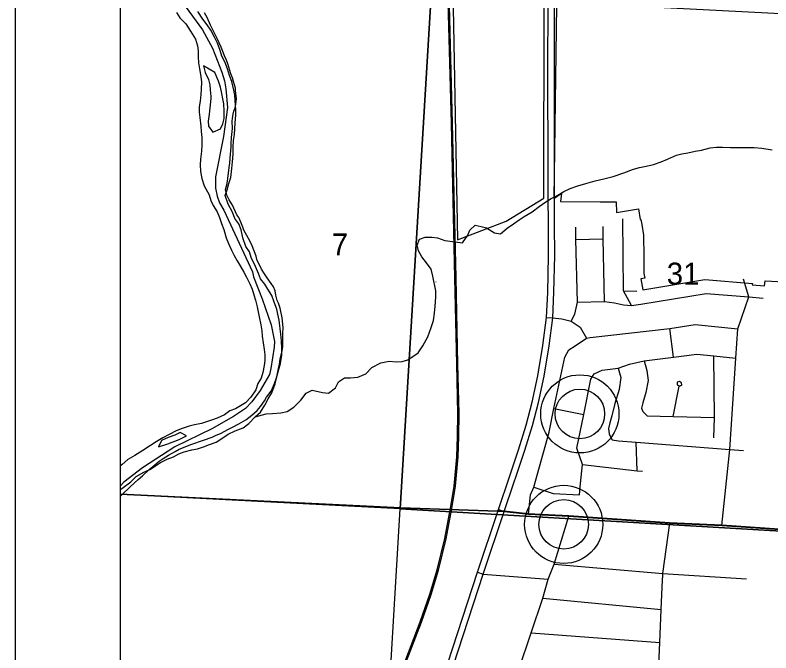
# Model space of a CAD drawing. Extents: x 0 to 42.5, y 0 to 22.
# Drawn here: x 2 to 2.72, y 18.908 to 19.515 of the extents above; entities that cross this region are included whole.
import ezdxf

# ---------------------------------------------------------------- set-up
doc = ezdxf.new("R2010")
doc.units = 0
for name, color, linetype in [('Default', 7, 'Continuous'), ('GM_X_County_Road', 7, 'Continuous'), ('GM_X_Interchange_Ramps', 7, 'Continuous'), ('GM_X_Major_River', 7, 'Continuous'), ('GM_X_Minor_River', 7, 'Continuous'), ('GM_X_Rail_Line', 7, 'Continuous'), ('GM_X_Section', 7, 'Continuous'), ('GM_X_Section_Text', 7, 'Continuous'), ('GM_X_Township_Road', 7, 'Continuous'), ('GM_X_Unincorporated', 7, 'Continuous'), ('GM_X_Unincorporated_Location', 7, 'Continuous'), ('GM_X_US_Route', 7, 'Continuous'), ('SH_Cut_Line', 7, 'Continuous'), ('SH_Data', 7, 'Continuous')]:
    doc.layers.add(name, color=color, linetype=linetype)

msp = doc.modelspace()

# ---------------------------------------------------------------- linework, layer by layer
at = {"layer": 'Default'}
for points in [[(2.41264, 19.76072), (2.42127, 19.30123), (2.46743, 19.31905), (2.50341, 19.34075), (2.50358, 19.5252)], [(2.51542, 19.52474), (2.51301, 19.34066), (2.52032, 19.34565), (2.51936, 19.33772), (2.55692, 19.33747), (2.57234, 19.33736), (2.57249, 19.32735), (2.59349, 19.33083), (2.59519, 19.32056), (2.59583, 19.32066), (2.5966, 19.31599), (2.5983, 19.30571), (2.59837, 19.29998), (2.59846, 19.29108), (2.59871, 19.26931), (2.59948, 19.26463), (2.59577, 19.26402), (2.59748, 19.25374), (2.6568, 19.26357), (2.70192, 19.25981), (2.7018, 19.25839), (2.7135, 19.25742), (2.71398, 19.26227), (2.75552, 19.25999)]]:
    msp.add_lwpolyline(points, dxfattribs=at)
at = {"layer": 'GM_X_County_Road'}
msp.add_lwpolyline([(2.46029, 19.0444), (2.46567, 19.0426), (2.48865, 19.04002), (2.52727, 19.03819), (2.62319, 19.03155), (2.67298, 19.02943), (2.73268, 19.0251)], dxfattribs=at)
at = {"layer": 'GM_X_Interchange_Ramps'}
for points in [[(2.15946, 19.52708), (2.17844, 19.5013), (2.18781, 19.48357), (2.19677, 19.46089), (2.19937, 19.45251), (2.20065, 19.4449), (2.20225, 19.42722), (2.19849, 19.39949), (2.19068, 19.36115), (2.1908, 19.35051), (2.19227, 19.3429), (2.19451, 19.33642), (2.19863, 19.32936), (2.22595, 19.27084), (2.22705, 19.26589), (2.23527, 19.24512), (2.24365, 19.22036), (2.24696, 19.20456), (2.24674, 19.19905), (2.24359, 19.17873), (2.24204, 19.17304), (2.23323, 19.15789), (2.22521, 19.14692), (2.2193, 19.14068), (2.20788, 19.13316), (2.18716, 19.12131), (2.152, 19.10424), (2.12118, 19.0841), (2.10348, 19.07053), (2.1, 19.06675), (2.1, 19.05902), (2.36716, 19.04598), (2.45932, 19.04306), (2.46556, 19.04286), (2.48854, 19.04029), (2.52716, 19.03846), (2.62308, 19.03181), (2.67287, 19.02969), (2.74103, 19.02475)], [(3.37078, 18.98615), (3.11995, 19.00104), (2.94956, 19.01199), (2.74103, 19.02475), (2.67287, 19.02969), (2.62308, 19.03181), (2.52716, 19.03846), (2.48854, 19.04029), (2.46556, 19.04286), (2.45932, 19.04306), (2.36716, 19.04598), (2.1, 19.05902), (2.1, 16.00757)]]:
    msp.add_lwpolyline(points, dxfattribs=at)
at = {"layer": 'GM_X_Major_River'}
for points in [[(2.1538, 19.51765), (2.1568, 19.51269), (2.16264, 19.50695), (2.16695, 19.49989), (2.17184, 19.49226), (2.1735, 19.48579), (2.17442, 19.48103), (2.17439, 19.47552), (2.17454, 19.46962), (2.17565, 19.46411), (2.17674, 19.45688), (2.17746, 19.45136), (2.17723, 19.44471), (2.17682, 19.43958), (2.17603, 19.43312), (2.17524, 19.428), (2.17521, 19.42268), (2.17575, 19.41754)], [(2.24651, 19.24185), (2.24427, 19.24814), (2.24052, 19.25424), (2.2377, 19.25901), (2.23375, 19.26398), (2.2317, 19.26912), (2.2289, 19.2758), (2.22478, 19.28456), (2.22311, 19.2899), (2.21973, 19.29486), (2.21693, 19.30305), (2.21509, 19.31067), (2.21304, 19.31657), (2.20909, 19.32154), (2.20685, 19.32763), (2.20292, 19.33526), (2.19993, 19.34345), (2.20186, 19.34895), (2.20341, 19.35483), (2.20534, 19.36071), (2.20634, 19.36907), (2.20695, 19.37553), (2.20756, 19.38294), (2.2076, 19.3894), (2.20783, 19.39567), (2.20881, 19.40136), (2.20963, 19.41276), (2.21025, 19.41979), (2.21027, 19.42473), (2.20922, 19.4388), (2.2083, 19.44375), (2.20646, 19.45193), (2.20403, 19.45765), (2.20217, 19.46412), (2.19956, 19.4706), (2.19694, 19.47613), (2.19527, 19.48146), (2.19266, 19.48832), (2.18985, 19.49404), (2.18629, 19.50072), (2.18291, 19.50587), (2.17877, 19.51141), (2.17408, 19.51866)], [(2.17945, 19.46693), (2.18093, 19.46065), (2.18411, 19.45398), (2.18541, 19.44865), (2.18576, 19.44389), (2.18629, 19.43781), (2.18643, 19.43576)], [(2.18643, 19.43576), (2.18486, 19.42071), (2.18387, 19.41426), (2.18403, 19.40951), (2.18836, 19.40359), (2.19558, 19.40696), (2.19788, 19.4117), (2.19905, 19.41663), (2.19909, 19.42366), (2.19856, 19.4307), (2.19764, 19.43546), (2.19673, 19.4404), (2.19562, 19.44649), (2.19377, 19.45221), (2.19002, 19.4604), (2.17945, 19.46693)], [(2.17575, 19.41754), (2.17683, 19.40955), (2.17718, 19.40442), (2.1779, 19.39852), (2.17786, 19.39149), (2.17745, 19.3856), (2.17664, 19.378), (2.17604, 19.3725), (2.17639, 19.36641), (2.17767, 19.35956), (2.18009, 19.3527), (2.18459, 19.34412), (2.18626, 19.33879), (2.18851, 19.33383), (2.19226, 19.32792), (2.19469, 19.32239), (2.19636, 19.31668), (2.19879, 19.31096), (2.20083, 19.30315), (2.20326, 19.29763), (2.20606, 19.29134), (2.20869, 19.28638), (2.2115, 19.28123), (2.21412, 19.27646), (2.21769, 19.27055), (2.22031, 19.26578), (2.22331, 19.25949), (2.22555, 19.25415), (2.22722, 19.24882), (2.2289, 19.24386), (2.23037, 19.23758), (2.23148, 19.23263), (2.2324, 19.22788), (2.23387, 19.22045), (2.23498, 19.21475), (2.23532, 19.20961), (2.23623, 19.20333), (2.23714, 19.19687), (2.23787, 19.19192), (2.23765, 19.18641), (2.23724, 19.18166), (2.23587, 19.17483), (2.23414, 19.16952), (2.23107, 19.1644), (2.22914, 19.15833), (2.22455, 19.15133), (2.21922, 19.14623), (2.2099, 19.1404), (2.20439, 19.13835), (2.19944, 19.13458), (2.19241, 19.13158), (2.18691, 19.12971), (2.1776, 19.12654), (2.17077, 19.12507), (2.16565, 19.12377), (2.15919, 19.12153), (2.15331, 19.11929), (2.14665, 19.11591), (2.14076, 19.11271), (2.1343, 19.10895), (2.12878, 19.10557), (2.12155, 19.10086), (2.11394, 19.09597), (2.10729, 19.09202), (2.10177, 19.08731), (2.1, 19.08564)], [(2.1, 19.06297), (2.10163, 19.06469), (2.11019, 19.07091), (2.11515, 19.07582), (2.12257, 19.08014), (2.12827, 19.08257), (2.13378, 19.08596), (2.13854, 19.08935), (2.14481, 19.09254), (2.15089, 19.09478), (2.15602, 19.09741), (2.16096, 19.09947), (2.16817, 19.10132), (2.17367, 19.10224), (2.17937, 19.10429), (2.18506, 19.10654), (2.19133, 19.10878), (2.19665, 19.11198), (2.20293, 19.11631), (2.20939, 19.11931), (2.21718, 19.1223), (2.22251, 19.12626), (2.22861, 19.13268), (2.23357, 19.13721), (2.23759, 19.14402), (2.24103, 19.14989), (2.24448, 19.15557), (2.24756, 19.16411), (2.2495, 19.17208), (2.25086, 19.17682), (2.2526, 19.18346), (2.25379, 19.19144), (2.25382, 19.19752), (2.25349, 19.20512), (2.25296, 19.21159), (2.25152, 19.2249), (2.25023, 19.23061), (2.24931, 19.23537), (2.24651, 19.24185)], [(2.1563, 19.11124), (2.1563, 19.11124), (2.16315, 19.11462), (2.1571, 19.11789), (2.15197, 19.11545), (2.1457, 19.11302), (2.13944, 19.11021), (2.13637, 19.10415)], [(2.13637, 19.10415), (2.14529, 19.10713), (2.1563, 19.11124)]]:
    msp.add_lwpolyline(points, dxfattribs=at)
at = {"layer": 'GM_X_Minor_River'}
for points in [[(2.39768, 19.26673), (2.39601, 19.2732), (2.39169, 19.2795), (2.38737, 19.28504), (2.38399, 19.29076), (2.38269, 19.29628), (2.385, 19.30197), (2.39032, 19.30384), (2.39676, 19.3038), (2.40207, 19.30319), (2.40925, 19.30048), (2.4191, 19.29928), (2.42591, 19.29829), (2.43088, 19.30567), (2.433, 19.31059), (2.43814, 19.31512), (2.44363, 19.31395), (2.44893, 19.31277), (2.45648, 19.30797), (2.46215, 19.3068), (2.46844, 19.31227), (2.47453, 19.31641), (2.47986, 19.32018), (2.4848, 19.32357), (2.49222, 19.32789), (2.49888, 19.33298), (2.50516, 19.33731), (2.51049, 19.34051), (2.51657, 19.34389), (2.52228, 19.34727), (2.52855, 19.35008), (2.53576, 19.3527), (2.54336, 19.35493), (2.55209, 19.35734), (2.56044, 19.35938), (2.56936, 19.3616), (2.57961, 19.36496), (2.58873, 19.36851), (2.59442, 19.37019), (2.60087, 19.37128), (2.60789, 19.37295), (2.61492, 19.37556), (2.621, 19.378), (2.62955, 19.38174), (2.63486, 19.38323), (2.64036, 19.38395), (2.64738, 19.38562), (2.65345, 19.38672), (2.6618, 19.38876), (2.66787, 19.38948), (2.67337, 19.38944), (2.68094, 19.3892), (2.70368, 19.38906), (2.71088, 19.38844), (2.72072, 19.38705)], [(2.22861, 19.13268), (2.23905, 19.13546), (2.24493, 19.1358), (2.25289, 19.13651), (2.25896, 19.1378), (2.26543, 19.14194), (2.27191, 19.14875), (2.27725, 19.15517), (2.28277, 19.15799), (2.2928, 19.15583), (2.29848, 19.15542), (2.30495, 19.16032), (2.30802, 19.166), (2.31353, 19.16976), (2.31922, 19.16992), (2.32642, 19.17044), (2.33383, 19.17382), (2.33955, 19.17967), (2.34811, 19.18418), (2.35626, 19.18565), (2.36289, 19.18503), (2.36839, 19.18538), (2.37389, 19.18686), (2.38379, 19.19383), (2.38818, 19.20027), (2.39278, 19.20898), (2.39625, 19.2177), (2.39818, 19.22453), (2.39917, 19.23156), (2.39978, 19.2382), (2.4004, 19.24675), (2.40062, 19.25264), (2.39769, 19.26664)], [(2.40051, 19.26125), (2.40061, 19.26105)]]:
    msp.add_lwpolyline(points, dxfattribs=at)
at = {"layer": 'GM_X_Rail_Line'}
for points in [[(2.1, 18.17792), (2.14457, 18.29396), (2.17654, 18.37756), (2.33207, 18.78921), (2.36704, 18.88549), (2.3869, 18.93734), (2.39596, 18.96355), (2.40293, 18.98689), (2.41025, 19.01669), (2.41583, 19.04561), (2.41931, 19.0667), (2.42175, 19.09458), (2.42245, 19.11392), (2.42262, 19.13604), (2.42161, 19.1829), (2.41977, 19.26504), (2.41656, 19.41217), (2.41219, 19.57384)], [(2.1, 18.18164), (2.15385, 18.32227), (2.17403, 18.37922), (2.33229, 18.79774), (2.36592, 18.88591), (2.38577, 18.93774), (2.39482, 18.96391), (2.40178, 18.98721), (2.40908, 19.01694), (2.41465, 19.04582), (2.41812, 19.06685), (2.42055, 19.09465), (2.42125, 19.11394), (2.42142, 19.13604), (2.42041, 19.18287), (2.41857, 19.26502), (2.41536, 19.41214), (2.41099, 19.57381)]]:
    msp.add_lwpolyline(points, dxfattribs=at)
at = {"layer": 'GM_X_Section'}
msp.add_lwpolyline([(2.39595, 19.53408), (2.36652, 19.04519), (2.10192, 19.05874), (2.10942, 19.06612), (2.11722, 19.07309), (2.12121, 19.07648), (2.12749, 19.08251), (2.1311, 19.08534), (2.137, 19.09042), (2.1408, 19.09324), (2.14593, 19.09625), (2.15238, 19.09963), (2.15618, 19.10188), (2.16814, 19.10675), (2.17933, 19.11067), (2.18768, 19.11329), (2.19129, 19.11516), (2.19546, 19.11685), (2.20306, 19.12117), (2.20761, 19.12323), (2.21312, 19.12604), (2.21958, 19.12999), (2.22528, 19.13432), (2.23042, 19.13884), (2.23365, 19.14261), (2.23728, 19.14789), (2.23938, 19.15148), (2.24186, 19.15469), (2.24357, 19.15696), (2.2451, 19.15998), (2.24702, 19.16452), (2.24932, 19.17075), (2.25068, 19.1787), (2.25165, 19.18287), (2.25243, 19.18797), (2.25379, 19.19384), (2.25476, 19.19952), (2.25501, 19.21202), (2.25504, 19.2177), (2.25413, 19.22698), (2.25248, 19.23608), (2.2506, 19.24102), (2.24948, 19.24348), (2.24818, 19.2486), (2.24744, 19.25278), (2.24594, 19.25638), (2.24388, 19.2598), (2.23992, 19.26493), (2.23729, 19.26873), (2.23466, 19.27329), (2.23372, 19.27557), (2.23147, 19.27955), (2.23016, 19.28259), (2.22942, 19.28563), (2.22792, 19.2898), (2.22661, 19.29284), (2.2253, 19.29644), (2.2223, 19.30252), (2.2176, 19.3105), (2.21667, 19.31315), (2.2148, 19.31808), (2.21293, 19.32245), (2.21124, 19.32511), (2.20692, 19.33422), (2.20373, 19.33935), (2.20167, 19.34372), (2.20036, 19.34921), (2.20153, 19.35375), (2.20211, 19.35716), (2.2025, 19.35962), (2.20388, 19.37003), (2.20446, 19.3742), (2.20486, 19.37912), (2.20568, 19.38991), (2.20569, 19.39294), (2.2061, 19.39862), (2.20708, 19.40733), (2.20674, 19.41415), (2.20694, 19.4168), (2.20772, 19.42096), (2.2083, 19.4238), (2.20945, 19.42682), (2.21004, 19.43023), (2.21063, 19.43572), (2.20991, 19.44311), (2.20973, 19.44576), (2.20806, 19.45183), (2.20694, 19.45544), (2.20544, 19.45923), (2.20358, 19.46568), (2.20246, 19.46891), (2.20114, 19.47213), (2.19946, 19.4765), (2.19628, 19.48465), (2.19234, 19.49282), (2.18934, 19.49927), (2.18597, 19.50554), (2.18297, 19.51294), (2.18015, 19.51731)], dxfattribs=at)
for points in [[(2.39595, 19.53408), (2.90759, 19.50738), (2.87643, 19.01565), (2.83799, 19.01773), (2.36652, 19.04519)], [(2.36652, 19.04519), (2.83799, 19.01773), (2.81447, 18.53809), (2.33788, 18.56407)]]:
    msp.add_lwpolyline(points, close=True, dxfattribs=at)
at = {"layer": 'GM_X_Township_Road'}
for p, q in [((2.53394, 19.3015), (2.55991, 19.30233)), ((2.57912, 19.25274), (2.59194, 19.25229)), ((2.62679, 19.18966), (2.62342, 19.2169)), ((2.51299, 19.14065), (2.5415, 19.13505)), ((2.5923, 19.08131), (2.59117, 19.10855)), ((2.51324, 18.99239), (2.52727, 19.03819)), ((2.5076, 18.97829), (2.51324, 18.99239)), ((2.5076, 18.97829), (2.51324, 18.99239)), ((2.5024, 18.9603), (2.61523, 18.94922)), ((2.49145, 18.92723), (2.61384, 18.91784))]:
    msp.add_line(p, q, dxfattribs=at)
for points in [[(2.58668, 19.23866), (2.57912, 19.25274), (2.57865, 19.32136)], [(2.52949, 19.22384), (2.53288, 19.23061), (2.53542, 19.24205), (2.53394, 19.3015), (2.53394, 19.31318)], [(2.56126, 19.24269), (2.55991, 19.30233), (2.56001, 19.31401)], [(2.67298, 19.02943), (2.68043, 19.1017), (2.68615, 19.18863), (2.6882, 19.21637), (2.69851, 19.24713), (2.69341, 19.26367)], [(2.53542, 19.24205), (2.56126, 19.24269), (2.57058, 19.24142), (2.57927, 19.2393), (2.58668, 19.23866), (2.59579, 19.23993), (2.65806, 19.2501), (2.69851, 19.24713), (2.71206, 19.24586)], [(2.50597, 19.22738), (2.51186, 19.2271), (2.52039, 19.22617), (2.52949, 19.22384), (2.53797, 19.21812), (2.54411, 19.20774)], [(2.54751, 19.20813), (2.62342, 19.2169), (2.6474, 19.22079), (2.6882, 19.21637)], [(2.48865, 19.04002), (2.49073, 19.05842), (2.49381, 19.06594), (2.50838, 19.11801), (2.51299, 19.14065), (2.52341, 19.18958), (2.52724, 19.1964), (2.53334, 19.20036), (2.54411, 19.20774), (2.54751, 19.20813)], [(2.53722, 19.05842), (2.53828, 19.06943), (2.54019, 19.08754), (2.53488, 19.10284), (2.5415, 19.13505), (2.54817, 19.16872), (2.55142, 19.17383), (2.55885, 19.17721), (2.57407, 19.17911), (2.5849, 19.18295), (2.59892, 19.18604), (2.62679, 19.18966), (2.64914, 19.19227), (2.66514, 19.19069), (2.68615, 19.18863)], [(2.66521, 19.11272), (2.6657, 19.13211), (2.66514, 19.19069)], [(2.59892, 19.18604), (2.60138, 19.17677), (2.60266, 19.16726), (2.60051, 19.15587), (2.59761, 19.14619), (2.59643, 19.14088), (2.59775, 19.13783), (2.60171, 19.13381), (2.62658, 19.13315), (2.6657, 19.13211)], [(2.57407, 19.17911), (2.57666, 19.17026), (2.57508, 19.15868), (2.57101, 19.1454), (2.5681, 19.13363), (2.56635, 19.12718), (2.5648, 19.12167), (2.56572, 19.11616), (2.56835, 19.11101), (2.57442, 19.10983), (2.59117, 19.10855), (2.68043, 19.1017), (2.69335, 19.10071)], [(2.62658, 19.13315), (2.63207, 19.16205), (2.63462, 19.16283), (2.63455, 19.16508), (2.63257, 19.16655), (2.63021, 19.16562), (2.63021, 19.16307), (2.63207, 19.16215)], [(2.54019, 19.08754), (2.5923, 19.08131), (2.59724, 19.08118)], [(2.49381, 19.06594), (2.51228, 19.05974), (2.53722, 19.05842)], [(2.61665, 18.981), (2.61676, 18.98348), (2.62319, 19.03155)], [(2.51324, 18.99239), (2.61676, 18.98348), (2.69624, 18.97857)], [(2.44032, 18.98489), (2.4457, 18.98309), (2.5076, 18.97829)], [(2.47952, 18.89221), (2.49145, 18.92723), (2.5024, 18.9603), (2.5076, 18.97829)], [(2.61144, 18.8641), (2.61227, 18.8827), (2.61384, 18.91784), (2.61523, 18.94922), (2.61649, 18.97753), (2.61665, 18.981)]]:
    msp.add_lwpolyline(points, dxfattribs=at)
at = {"layer": 'GM_X_Unincorporated'}
msp.add_lwpolyline([(2.1, 19.05692), (2.1, 18.5541), (2.33587, 18.53945), (2.33788, 18.56407), (2.36652, 19.04519), (2.10192, 19.05874)], close=True, dxfattribs=at)
for centre, radius in [((2.53767, 19.13555), 0.0372), ((2.53767, 19.13555), 0.02358), ((2.52228, 19.03037), 0.0372), ((2.52228, 19.03037), 0.02358)]:
    msp.add_circle(centre, radius, dxfattribs=at)
at = {"layer": 'GM_X_Unincorporated_Location'}
for p, q in [((2.53767, 19.13555), (2.53767, 19.13555)), ((2.52228, 19.03037), (2.52228, 19.03037))]:
    msp.add_line(p, q, dxfattribs=at)
at = {"layer": 'GM_X_US_Route'}
msp.add_line((2.46567, 19.0426), (2.4752, 19.07101), dxfattribs=at)
for points in [[(2.46029, 19.0444), (2.47074, 19.07556), (2.4793, 19.10144), (2.48654, 19.12491), (2.49224, 19.14684), (2.49772, 19.17185), (2.50255, 19.20058), (2.50597, 19.22738), (2.50712, 19.25099), (2.50778, 19.28609), (2.50712, 19.45833), (2.50756, 19.53173)], [(2.51366, 19.31627), (2.51348, 19.45822), (2.51348, 19.5247)], [(2.4752, 19.07101), (2.47664, 19.07528), (2.48519, 19.10116), (2.49243, 19.12462), (2.49813, 19.14656), (2.50361, 19.17156), (2.50844, 19.20029), (2.51186, 19.2271), (2.51304, 19.2514), (2.5137, 19.28649), (2.51366, 19.31627)], [(2.31976, 18.62226), (2.3204, 18.62418), (2.33388, 18.66357), (2.34923, 18.70972), (2.4121, 18.89829), (2.44032, 18.98489), (2.45943, 19.04279), (2.46029, 19.0444)], [(2.32618, 18.62258), (2.3401, 18.66327), (2.35546, 18.70942), (2.41749, 18.89648), (2.4457, 18.98309), (2.46567, 19.0426)]]:
    msp.add_lwpolyline(points, dxfattribs=at)
at = {"layer": 'SH_Cut_Line'}
msp.add_lwpolyline([(5.48884, 19.405), (5.50057, 19.55251), (5.51061, 19.66936), (5.5156, 19.73605), (5.52526, 19.85376), (5.53536, 19.98472), (5.54606, 20.11658), (5.56474, 20.34561), (5.56563, 20.35496), (5.56586, 20.35729), (5.60252, 20.8068), (5.60957, 20.9), (2.1, 20.9), (2.1, 16.00757)], dxfattribs=at)
at = {"layer": 'SH_Data'}
for p, q in [((2, 21), (2, 14)), ((2.1, 20.9), (2.1, 14.1))]:
    msp.add_line(p, q, dxfattribs=at)

# ---------------------------------------------------------------- texts
at = {"layer": 'GM_X_Section_Text'}
for s, height, p in [('7', 0.02093, (2.30141, 19.28637)), ('31', 0.020928, (2.62037, 19.25861))]:
    msp.add_text(s, height=height, rotation=0.00001, dxfattribs=at).set_placement(p)

doc.saveas('drawing.dxf')
